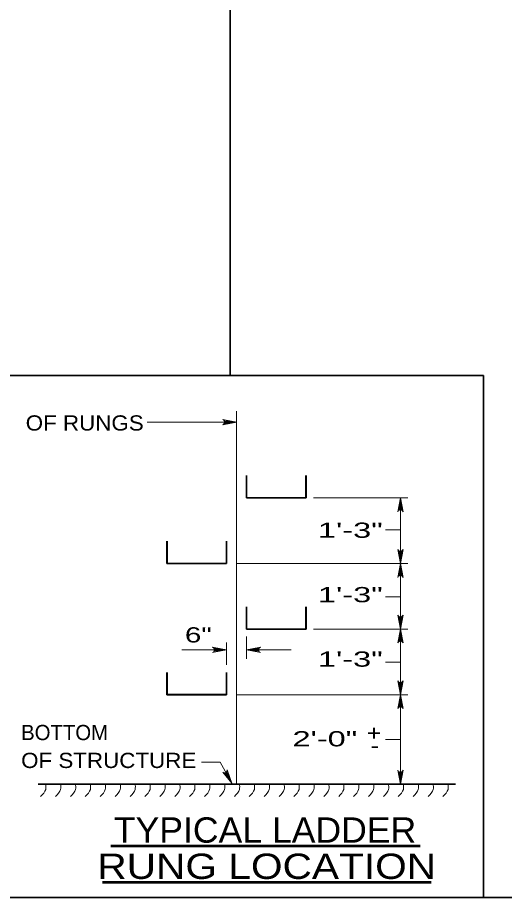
# Model space of a CAD drawing. Extents: x 15 to 140, y -57 to 117.
# Drawn here: x 63 to 95.7, y -2.1 to 56.9 of the extents above; entities that cross this region are included whole.
import ezdxf
from ezdxf.enums import TextEntityAlignment as Align

# ---------------------------------------------------------------- set-up
doc = ezdxf.new("R2010")
doc.units = 0
doc.header["$LTSCALE"] = 0.41
for name, color, linetype, lineweight in [('1', 7, 'Continuous', 35), ('10', 7, 'Continuous', 13), ('12', 7, 'Continuous', 53), ('13', 7, 'Continuous', 53), ('6', 7, 'Continuous', 13)]:
    doc.layers.add(name, color=color, linetype=linetype, lineweight=lineweight)

msp = doc.modelspace()

# ---------------------------------------------------------------- linework, layer by layer
at = {"layer": '1'}
for p, q in [((77.2522, 32.9068), (77.2522, 117.3839)), ((60.2522, 32.9068), (94.2522, 32.9068)), ((94.2522, -2.0932), (94.2522, 32.9068)), ((78.3531, 24.6947), (78.3531, 26.1947)), ((78.3581, 24.6947), (78.3581, 26.1947)), ((82.3481, 24.6947), (82.3481, 26.1947)), ((82.3531, 24.6947), (82.3531, 26.1947)), ((78.3531, 24.6997), (82.3531, 24.6997)), ((78.3531, 24.6947), (82.3531, 24.6947)), ((73.0198, 20.2947), (73.0198, 21.7947)), ((73.0247, 20.2947), (73.0247, 21.7947)), ((77.0147, 20.2947), (77.0147, 21.7947)), ((77.0198, 20.2947), (77.0198, 21.7947)), ((73.0198, 20.2997), (77.0198, 20.2997)), ((73.0198, 20.2947), (77.0198, 20.2947)), ((78.3531, 15.8947), (78.3531, 17.3947)), ((78.3581, 15.8947), (78.3581, 17.3947)), ((82.3481, 15.8947), (82.3481, 17.3947)), ((82.3531, 15.8947), (82.3531, 17.3947)), ((78.3531, 15.8997), (82.3531, 15.8997)), ((78.3531, 15.8947), (82.3531, 15.8947)), ((73.0198, 11.4947), (73.0198, 12.9947)), ((73.0247, 11.4947), (73.0247, 12.9947)), ((77.0147, 11.4947), (77.0147, 12.9947)), ((77.0198, 11.4947), (77.0198, 12.9947)), ((73.0198, 11.4997), (77.0198, 11.4997)), ((73.0198, 11.4947), (77.0198, 11.4947)), ((64.3769, 5.4947), (92.3769, 5.4947)), ((15.0728, -2.0932), (140.4342, -2.0932))]:
    msp.add_line(p, q, dxfattribs=at)
at = {"layer": '10'}
for p, q in [((77.6864, 5.4947), (77.6864, 30.4947)), ((77.6991, 29.7733), (71.6864, 29.7733)), ((82.8531, 24.6947), (89.1864, 24.6947)), ((88.6864, 5.4947), (88.6864, 24.6947)), ((88.6781, 22.5434), (87.6781, 22.5434)), ((77.6864, 20.2947), (89.1864, 20.2947)), ((88.6864, 18.0553), (87.6864, 18.0553)), ((78.3581, 15.3947), (78.3581, 13.8947)), ((82.8531, 15.8947), (89.1864, 15.8947)), ((77.0198, 13.4947), (77.0198, 14.9947)), ((74.0198, 14.5006), (77.0198, 14.5006)), ((78.3581, 14.5006), (81.3581, 14.5006)), ((88.6864, 13.6838), (87.6864, 13.6838)), ((77.6864, 11.4947), (89.1864, 11.4947)), ((88.6864, 8.4962), (87.6864, 8.4962))]:
    msp.add_line(p, q, dxfattribs=at)
for points in [[(77.6991, 29.7733), (76.7671, 29.5986), (76.8389, 29.6483), (76.8759, 29.7108), (76.8866, 29.7733), (76.8759, 29.8358), (76.8389, 29.8983), (76.7671, 29.9481), (77.6991, 29.7733), (76.8389, 29.8983), (76.8759, 29.8358), (77.6991, 29.7733), (76.8866, 29.7733), (76.8759, 29.7108), (77.6991, 29.7733), (76.8389, 29.6483)], [(88.6864, 24.6947), (88.8612, 23.7626), (88.8114, 23.8344), (88.7489, 23.8715), (88.6864, 23.8822), (88.6239, 23.8715), (88.5614, 23.8344), (88.5117, 23.7626), (88.6864, 24.6947), (88.5614, 23.8344), (88.6239, 23.8715), (88.6864, 24.6947), (88.6864, 23.8822), (88.7489, 23.8715), (88.6864, 24.6947), (88.8114, 23.8344)], [(88.6864, 20.2947), (88.8612, 21.2268), (88.8114, 21.1549), (88.7489, 21.1179), (88.6864, 21.1072), (88.6239, 21.1179), (88.5614, 21.1549), (88.5117, 21.2268), (88.6864, 20.2947), (88.5614, 21.1549), (88.6239, 21.1179), (88.6864, 20.2947), (88.6864, 21.1072), (88.7489, 21.1179), (88.6864, 20.2947), (88.8114, 21.1549)], [(88.6864, 20.2947), (88.8612, 19.3626), (88.8114, 19.4344), (88.7489, 19.4715), (88.6864, 19.4822), (88.6239, 19.4715), (88.5614, 19.4344), (88.5117, 19.3626), (88.6864, 20.2947), (88.5614, 19.4344), (88.6239, 19.4715), (88.6864, 20.2947), (88.6864, 19.4822), (88.7489, 19.4715), (88.6864, 20.2947), (88.8114, 19.4344)], [(88.6864, 15.8947), (88.8612, 16.8268), (88.8114, 16.7549), (88.7489, 16.7179), (88.6864, 16.7072), (88.6239, 16.7179), (88.5614, 16.7549), (88.5117, 16.8268), (88.6864, 15.8947), (88.5614, 16.7549), (88.6239, 16.7179), (88.6864, 15.8947), (88.6864, 16.7072), (88.7489, 16.7179), (88.6864, 15.8947), (88.8114, 16.7549)], [(88.6864, 15.8947), (88.8612, 14.9626), (88.8114, 15.0344), (88.7489, 15.0715), (88.6864, 15.0822), (88.6239, 15.0715), (88.5614, 15.0344), (88.5117, 14.9626), (88.6864, 15.8947), (88.5614, 15.0344), (88.6239, 15.0715), (88.6864, 15.8947), (88.6864, 15.0822), (88.7489, 15.0715), (88.6864, 15.8947), (88.8114, 15.0344)], [(77.0198, 14.5006), (76.0877, 14.3258), (76.1595, 14.3756), (76.1965, 14.4381), (76.2073, 14.5006), (76.1965, 14.5631), (76.1595, 14.6256), (76.0877, 14.6754), (77.0198, 14.5006), (76.1595, 14.6256), (76.1965, 14.5631), (77.0198, 14.5006), (76.2073, 14.5006), (76.1965, 14.4381), (77.0198, 14.5006), (76.1595, 14.3756)], [(78.3581, 14.5006), (79.2902, 14.6754), (79.2183, 14.6256), (79.1813, 14.5631), (79.1706, 14.5006), (79.1813, 14.4381), (79.2183, 14.3756), (79.2902, 14.3258), (78.3581, 14.5006), (79.2183, 14.3756), (79.1813, 14.4381), (78.3581, 14.5006), (79.1706, 14.5006), (79.1813, 14.5631), (78.3581, 14.5006), (79.2183, 14.6256)], [(88.6864, 11.4947), (88.8612, 12.4268), (88.8114, 12.3549), (88.7489, 12.3179), (88.6864, 12.3072), (88.6239, 12.3179), (88.5614, 12.3549), (88.5117, 12.4268), (88.6864, 11.4947), (88.5614, 12.3549), (88.6239, 12.3179), (88.6864, 11.4947), (88.6864, 12.3072), (88.7489, 12.3179), (88.6864, 11.4947), (88.8114, 12.3549)], [(88.6864, 11.4947), (88.8612, 10.5626), (88.8114, 10.6344), (88.7489, 10.6715), (88.6864, 10.6822), (88.6239, 10.6715), (88.5614, 10.6344), (88.5117, 10.5626), (88.6864, 11.4947), (88.5614, 10.6344), (88.6239, 10.6715), (88.6864, 11.4947), (88.6864, 10.6822), (88.7489, 10.6715), (88.6864, 11.4947), (88.8114, 10.6344)], [(75.3346, 6.9634), (76.6003, 6.9634), (77.3695, 5.5685)], [(77.3695, 5.5685), (76.7664, 6.3003), (76.8446, 6.2614), (76.9172, 6.2592), (76.9771, 6.28), (77.0267, 6.3196), (77.0635, 6.3822), (77.0724, 6.4691), (77.3695, 5.5685), (77.0635, 6.3822), (77.0267, 6.3196), (77.3695, 5.5685), (76.9771, 6.28), (76.9172, 6.2592), (77.3695, 5.5685), (76.8446, 6.2614)], [(88.6864, 5.4947), (88.5117, 6.4268), (88.5614, 6.3549), (88.6239, 6.3179), (88.6864, 6.3072), (88.7489, 6.3179), (88.8114, 6.3549), (88.8612, 6.4268), (88.6864, 5.4947), (88.8114, 6.3549), (88.7489, 6.3179), (88.6864, 5.4947), (88.6864, 6.3072), (88.6239, 6.3179), (88.6864, 5.4947), (88.5614, 6.3549)]]:
    msp.add_lwpolyline(points, dxfattribs=at)
at = {"layer": '12'}
for p, q in [((69.2519, 1.3554), (90.0139, 1.3554)), ((68.6905, -1.069), (90.7428, -1.069))]:
    msp.add_line(p, q, dxfattribs=at)
at = {"layer": '6'}
for points in [[(64.8849, 5.5249), (64.8849, 5.1497), (64.544, 4.6723)], [(65.8849, 5.5249), (65.8849, 5.1497), (65.544, 4.6723)], [(66.8849, 5.5249), (66.8849, 5.1497), (66.544, 4.6723)], [(67.8849, 5.5249), (67.8849, 5.1497), (67.544, 4.6723)], [(68.8849, 5.5249), (68.8849, 5.1497), (68.544, 4.6723)], [(69.8849, 5.5249), (69.8849, 5.1497), (69.544, 4.6723)], [(70.8849, 5.5249), (70.8849, 5.1497), (70.544, 4.6723)], [(71.8849, 5.5249), (71.8849, 5.1497), (71.544, 4.6723)], [(72.8849, 5.5249), (72.8849, 5.1497), (72.544, 4.6723)], [(73.8849, 5.5249), (73.8849, 5.1497), (73.544, 4.6723)], [(74.8849, 5.5249), (74.8849, 5.1497), (74.544, 4.6723)], [(75.8849, 5.5249), (75.8849, 5.1497), (75.544, 4.6723)], [(76.8849, 5.5249), (76.8849, 5.1497), (76.544, 4.6723)], [(77.8849, 5.5249), (77.8849, 5.1497), (77.544, 4.6723)], [(78.8849, 5.5249), (78.8849, 5.1497), (78.544, 4.6723)], [(79.8849, 5.5249), (79.8849, 5.1497), (79.544, 4.6723)], [(80.8849, 5.5249), (80.8849, 5.1497), (80.544, 4.6723)], [(81.8849, 5.5249), (81.8849, 5.1497), (81.544, 4.6723)], [(82.8849, 5.5249), (82.8849, 5.1497), (82.544, 4.6723)], [(83.8849, 5.5249), (83.8849, 5.1497), (83.544, 4.6723)], [(84.8849, 5.5249), (84.8849, 5.1497), (84.544, 4.6723)], [(85.8849, 5.5249), (85.8849, 5.1497), (85.544, 4.6723)], [(86.8849, 5.5249), (86.8849, 5.1497), (86.544, 4.6723)], [(87.8849, 5.5249), (87.8849, 5.1497), (87.544, 4.6723)], [(88.8849, 5.5249), (88.8849, 5.1497), (88.544, 4.6723)], [(89.8849, 5.5249), (89.8849, 5.1497), (89.544, 4.6723)], [(90.8849, 5.5249), (90.8849, 5.1497), (90.544, 4.6723)], [(91.8849, 5.5249), (91.8849, 5.1497), (91.544, 4.6723)]]:
    msp.add_spline(points, degree=3, dxfattribs=at)

# ---------------------------------------------------------------- texts
at = {"layer": '12', "width": 1.1}
for s, p in [('OF RUNGS', (63.5432, 29.2048)), ('OF STRUCTURE', (63.2359, 6.5814))]:
    msp.add_text(s, height=1.02, dxfattribs=at).set_placement(p)
at = {"layer": '12'}
msp.add_text('BOTTOM', height=1.02, dxfattribs=at).set_placement((63.2359, 8.4514))
for s, width, p in [('TYPICAL LADDER', 1.05, (79.6025, 1.5744)), ('RUNG LOCATION', 1.2, (79.7167, -0.8565))]:
    msp.add_text(s, height=1.7, dxfattribs=dict(at, width=width)).set_placement(p, align=Align.CENTER)
at = {"layer": '13'}
for s, width, p in [('1\'-3"', 1.6, (85.3282, 22.015)), ('1\'-3"', 1.6, (85.3282, 17.6947)), ('6"', 1.45, (75.1286, 14.9976)), ('1\'-3"', 1.6, (85.3282, 13.3745)), ('2\'-0"', 1.6, (83.6176, 8.0326)), ('+', 1.2, (86.9174, 8.4265)), ('-', 1.3, (86.9638, 7.5917))]:
    msp.add_text(s, height=1.02, dxfattribs=dict(at, width=width)).set_placement(p, align=Align.CENTER)

doc.saveas('drawing.dxf')
